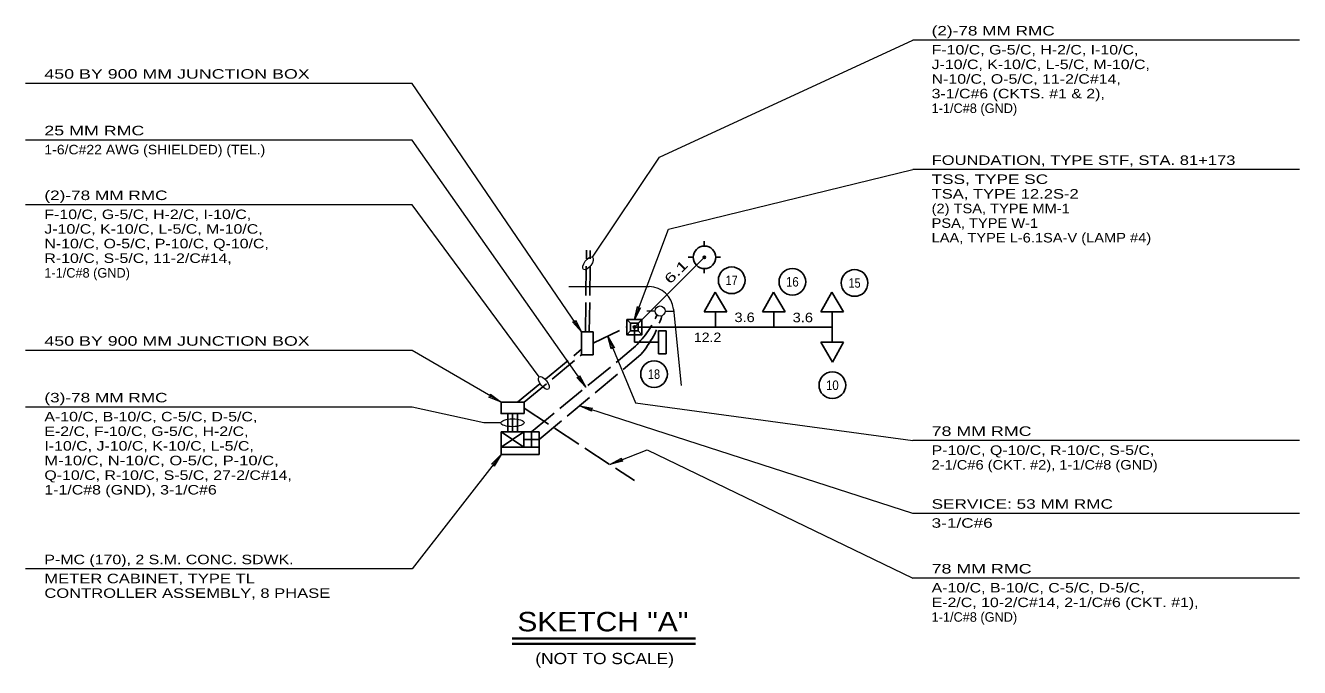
# Model space of a CAD drawing. Extents: x 168203 to 169863, y 223196 to 223870.
# Drawn here: x 168650.9 to 168729.5, y 223388.5 to 223428.2 of the extents above; entities that cross this region are included whole.
import ezdxf
from ezdxf.enums import TextEntityAlignment as Align

# ---------------------------------------------------------------- set-up
doc = ezdxf.new("R2010")
doc.units = 0
doc.header["$LTSCALE"] = 0.3
doc.header["$PDMODE"] = 32
doc.header["$PDSIZE"] = 0.15
doc.linetypes.add('LONG_DASH_SHORT_DASH', pattern=[9.9, 6, -1.2, 1.5, -1.2])
doc.linetypes.add('LONG_DASHED', pattern=[7.5, 6, -1.5])
for name, color, linetype, lineweight in [('1', 7, 'Continuous', 13), ('3', 7, 'Continuous', 25), ('31', 7, 'Continuous', 25), ('5', 7, 'Continuous', 25), ('6', 7, 'LONG_DASHED', 25), ('7', 7, 'Continuous', 25), ('9', 7, 'Continuous', 13)]:
    doc.layers.add(name, color=color, linetype=linetype, lineweight=lineweight)

msp = doc.modelspace()

# ---------------------------------------------------------------- linework, layer by layer
at = {"layer": '1'}
for p, q in [((168684.4082, 223412.0372), (168689.3593, 223412.0372)), ((168689.7236, 223410.5295), (168689.2236, 223410.5295)), ((168690.3486, 223410.5295), (168690.8486, 223410.5295)), ((168690.8555, 223410.6453), (168691.3411, 223405.9231))]:
    msp.add_line(p, q, dxfattribs=at)
msp.add_circle((168690.0361, 223410.5295), 0.3125, dxfattribs=at)
msp.add_arc((168689.3593, 223410.5372), 1.5, 4.13349, 90.00005, dxfattribs=at)
at = {"layer": '3'}
for p, q in [((168687.9774, 223410.0071), (168688.2123, 223409.7721)), ((168688.9171, 223410.0071), (168688.6822, 223409.7721)), ((168687.9774, 223409.0673), (168688.2123, 223409.3023)), ((168688.9171, 223409.0673), (168688.6822, 223409.3023))]:
    msp.add_line(p, q, dxfattribs=at)
for points in [[(168687.9774, 223410.0071), (168688.9171, 223410.0071), (168688.9171, 223409.0673), (168687.9774, 223409.0673)], [(168688.2123, 223409.7721), (168688.6822, 223409.7721), (168688.6822, 223409.3023), (168688.2123, 223409.3023)]]:
    msp.add_lwpolyline(points, close=True, dxfattribs=at)
msp.add_point((168688.4563, 223409.5372), dxfattribs=at)
at = {"layer": '31'}
for p, q in [((168688.4563, 223409.5372), (168692.7697, 223413.8506)), ((168693.4563, 223409.5372), (168693.4563, 223410.477)), ((168697.0563, 223409.5372), (168697.0563, 223410.477)), ((168700.6563, 223409.5372), (168700.6563, 223410.477)), ((168688.4563, 223409.5372), (168700.6563, 223409.5372)), ((168688.4563, 223408.5974), (168688.4563, 223409.5372)), ((168700.6563, 223409.5372), (168700.6563, 223408.5974)), ((168688.4563, 223408.5974), (168689.9392, 223408.5974))]:
    msp.add_line(p, q, dxfattribs=at)
at = {"layer": '31', "linetype": 'LONG_DASH_SHORT_DASH'}
for points in [[(168693.4382, 223411.6968), (168692.7515, 223410.477), (168693.4563, 223410.477), (168694.1611, 223410.477)], [(168697.0382, 223411.6968), (168696.3515, 223410.477), (168697.0563, 223410.477), (168697.7611, 223410.477)], [(168700.6382, 223411.6968), (168699.9515, 223410.477), (168700.6563, 223410.477), (168701.3611, 223410.477)], [(168690.409, 223407.8835), (168690.409, 223409.3022), (168689.9392, 223409.3022), (168689.9392, 223407.8835)], [(168700.6744, 223407.3776), (168701.3611, 223408.5974), (168700.6563, 223408.5974), (168699.9515, 223408.5974)]]:
    msp.add_lwpolyline(points, close=True, dxfattribs=at)
at = {"layer": '31'}
for centre in [(168694.4555, 223412.4268), (168698.2014, 223412.3337), (168702.0404, 223412.2639), (168689.6626, 223406.6306), (168700.669, 223405.9457)]:
    msp.add_circle(centre, 0.8236, dxfattribs=at)
at = {"layer": '5'}
for p, q in [((168680.2184, 223403.0683), (168681.628, 223402.1285)), ((168681.628, 223403.0683), (168680.2184, 223402.1285)), ((168680.2184, 223403.0683), (168682.5678, 223403.0683)), ((168680.2184, 223403.0683), (168680.2184, 223402.1285)), ((168681.628, 223402.1285), (168681.628, 223403.0683)), ((168681.628, 223402.5984), (168682.5678, 223402.5984)), ((168682.1069, 223403.0683), (168682.1069, 223402.1285)), ((168682.5678, 223403.0683), (168682.5678, 223402.1285)), ((168682.5678, 223402.1285), (168680.2184, 223402.1285)), ((168680.2184, 223402.1285), (168680.2184, 223401.6586)), ((168682.5678, 223402.1285), (168682.5678, 223401.6586)), ((168682.5678, 223401.6586), (168680.2184, 223401.6586))]:
    msp.add_line(p, q, dxfattribs=at)
for points in [[(168685.9002, 223409.2466), (168685.9002, 223407.8279), (168685.1954, 223407.8279), (168685.1954, 223409.2466)], [(168681.6376, 223404.1893), (168680.2189, 223404.1893), (168680.2189, 223404.8941), (168681.6376, 223404.8941)]]:
    msp.add_lwpolyline(points, close=True, dxfattribs=at)
at = {"layer": '6'}
for p, q in [((168685.4307, 223409.2466), (168685.4911, 223414.2809)), ((168685.669, 223409.2466), (168685.7294, 223414.2781)), ((168685.9002, 223408.5373), (168687.9774, 223409.5372)), ((168681.2373, 223404.8941), (168685.1954, 223408.1662)), ((168682.1069, 223403.0683), (168688.4013, 223408.2467)), ((168681.6376, 223404.8941), (168685.1864, 223407.8279)), ((168682.5678, 223402.5984), (168688.8574, 223407.8459)), ((168680.6326, 223404.1893), (168680.6326, 223403.0683)), ((168680.9282, 223404.1893), (168680.9282, 223403.0683)), ((168681.232, 223404.1893), (168681.232, 223403.0683)), ((168681.6376, 223404.5372), (168688.4522, 223400.0552))]:
    msp.add_line(p, q, dxfattribs=at)
for centre, radius, start, end in [((168684.0978, 223412.8293), 6.2865, 313.20139, 336.09784), ((168683.7004, 223412.1673), 6.7282, 320.03766, 343.32646)]:
    msp.add_arc(centre, radius, start, end, dxfattribs=at)
at = {"layer": '7'}
for p, q in [((168692.7569, 223414.5406), (168692.7633, 223414.8538)), ((168691.7601, 223413.8506), (168692.0796, 223413.8506)), ((168693.4726, 223413.8506), (168693.7601, 223413.8569)), ((168692.7634, 223412.8602), (168692.757, 223413.1477))]:
    msp.add_line(p, q, dxfattribs=at)
msp.add_circle((168692.7729, 223413.8474), 0.6965, dxfattribs=at)
msp.add_point((168692.7697, 223413.8506), dxfattribs=at)
at = {"layer": '9'}
for p, q in [((168729.5032, 223427.2662), (168705.6297, 223427.2662)), ((168674.7418, 223424.5965), (168650.8683, 223424.5965)), ((168685.1864, 223409.2466), (168674.7418, 223424.5965)), ((168674.7418, 223421.0965), (168650.8683, 223421.0965)), ((168685.4457, 223405.8152), (168674.7418, 223421.0965)), ((168729.5032, 223419.2662), (168705.6297, 223419.2662)), ((168674.7418, 223417.0965), (168650.8683, 223417.0965)), ((168682.5718, 223406.4583), (168674.7418, 223417.0965)), ((168674.7418, 223408.0965), (168650.8683, 223408.0965)), ((168680.2189, 223404.8941), (168674.7418, 223408.0965)), ((168674.7418, 223404.5965), (168650.8683, 223404.5965)), ((168705.6297, 223398.0247), (168685.0632, 223404.6804)), ((168729.5032, 223402.5247), (168705.6297, 223402.5247)), ((168680.2184, 223401.6586), (168674.7418, 223394.5965)), ((168729.5032, 223398.0247), (168705.6297, 223398.0247)), ((168674.7418, 223394.5965), (168650.8683, 223394.5965)), ((168729.5032, 223394.0247), (168705.6297, 223394.0247))]:
    msp.add_line(p, q, dxfattribs=at)
at = {"layer": '9', "lineweight": 35}
for p, q in [((168680.917, 223390.3044), (168692.2328, 223390.3044)), ((168680.917, 223389.957), (168692.2328, 223389.957))]:
    msp.add_line(p, q, dxfattribs=at)
at = {"layer": '9'}
for points in [[(168685.8686, 223413.8609), (168689.9984, 223420.0364), (168705.6297, 223427.2662)], [(168688.4473, 223410.0071), (168690.5609, 223415.5865), (168705.6297, 223419.2662)], [(168686.8076, 223408.9741), (168688.5107, 223404.8546), (168705.6297, 223402.5247)], [(168680.2142, 223403.6181), (168679.151, 223403.618), (168674.7418, 223404.5965)], [(168686.9396, 223401.05), (168689.248, 223401.9513), (168705.6297, 223394.0247)]]:
    msp.add_lwpolyline(points, dxfattribs=at)
for points in [[(168688.8284, 223410.7324), (168688.4473, 223410.0071), (168688.634, 223410.8061), (168688.7066, 223410.6915)], [(168684.8111, 223409.9749), (168685.1864, 223409.2466), (168684.6393, 223409.858), (168684.7747, 223409.8517)], [(168687.0265, 223408.1845), (168686.8076, 223408.9741), (168687.2185, 223408.2639), (168687.0872, 223408.2977)], [(168685.0605, 223406.5384), (168685.4457, 223405.8152), (168684.8903, 223406.4191), (168685.0258, 223406.4147)], [(168679.567, 223405.3904), (168680.2189, 223404.8941), (168679.4621, 223405.211), (168679.5871, 223405.2635)], [(168685.8064, 223404.3354), (168685.0632, 223404.6804), (168685.8704, 223404.5331), (168685.7595, 223404.4551)], [(168679.6414, 223401.0768), (168680.2184, 223401.6586), (168679.8057, 223400.9495), (168679.7699, 223401.0802)], [(168687.7334, 223401.2532), (168686.9396, 223401.05), (168687.6578, 223401.4468), (168687.6214, 223401.3162)]]:
    msp.add_lwpolyline(points, close=True, dxfattribs=at)
for centre, major_axis, ratio in [((168685.593, 223413.4775), (-0.2756, -0.3835), 0.453047), ((168682.864, 223406.0826), (-0.2922, 0.3757), 0.448277), ((168680.9282, 223403.6243), (0.714, 0.0062), 0.338213)]:
    msp.add_ellipse(centre, major_axis=major_axis, ratio=ratio, dxfattribs=at)

# ---------------------------------------------------------------- texts
at = {"layer": '31', "width": 1.5}
msp.add_text('6.1', height=0.5873, rotation=45, dxfattribs=at).set_placement((168691.231, 223412.7362), align=Align.CENTER)
at = {"layer": '31'}
for s, width, p in [('17', 0.85, (168694.4555, 223412.1332)), ('16', 0.9, (168698.2014, 223412.0401)), ('15', 0.85, (168702.0404, 223411.9703)), ('3.6', 1.15, (168695.2532, 223409.8468)), ('3.6', 1.15, (168698.8479, 223409.8372)), ('12.2', 1.1, (168692.969, 223408.6108)), ('18', 0.85, (168689.6626, 223406.337)), ('10', 0.9, (168700.669, 223405.6521))]:
    msp.add_text(s, height=0.5873, dxfattribs=dict(at, width=width)).set_placement(p, align=Align.CENTER)
at = {"layer": '9'}
for s, height, width, p in [('(2)-78 MM RMC                        ', 0.5873, 1.35, (168706.7954, 223427.5554)), ('F-10/C, G-5/C, H-2/C, I-10/C,', 0.5873, 1.25, (168706.7954, 223426.3807)), ('450 BY 900 MM JUNCTION BOX           ', 0.5873, 1.4, (168652.034, 223424.8857)), ('J-10/C, K-10/C, L-5/C, M-10/C,', 0.5873, 1.25, (168706.7954, 223425.477)), ('N-10/C, O-5/C, 11-2/C#14,  ', 0.5873, 1.25, (168706.7954, 223424.5734)), ('3-1/C#6 (CKTS. #1 & 2),  ', 0.5873, 1.25, (168706.7954, 223423.6698)), ('25 MM RMC                            ', 0.5873, 1.4, (168652.034, 223421.3857)), ('1-6/C#22 AWG (SHIELDED) (TEL.)        ', 0.5873, 1.1, (168652.034, 223420.211)), ('FOUNDATION, TYPE STF, STA. 81+173     ', 0.5873, 1.3, (168706.7954, 223419.5554)), ('TSS, TYPE SC                         ', 0.5873, 1.35, (168706.7954, 223418.3807)), ('(2)-78 MM RMC                        ', 0.5873, 1.35, (168652.034, 223417.3857)), ('TSA, TYPE 12.2S-2                    ', 0.5873, 1.3, (168706.7954, 223417.477)), ('F-10/C, G-5/C, H-2/C, I-10/C,', 0.5873, 1.25, (168652.034, 223416.211)), ('(2) TSA, TYPE MM-1                   ', 0.5873, 1.15, (168706.7954, 223416.5734)), ('J-10/C, K-10/C, L-5/C, M-10/C,', 0.5873, 1.25, (168652.034, 223415.3073)), ('PSA, TYPE W-1                    ', 0.5873, 1.15, (168706.7954, 223415.6698)), ('LAA, TYPE L-6.1SA-V (LAMP #4)         ', 0.5873, 1.15, (168706.7954, 223414.7662)), ('N-10/C, O-5/C, P-10/C, Q-10/C,  ', 0.5873, 1.25, (168652.034, 223414.4037)), ('R-10/C, S-5/C, 11-2/C#14,       ', 0.5873, 1.25, (168652.034, 223413.5001)), ('450 BY 900 MM JUNCTION BOX           ', 0.5873, 1.4, (168652.034, 223408.3857)), ('(3)-78 MM RMC                          ', 0.5873, 1.35, (168652.034, 223404.8857)), ('A-10/C, B-10/C, C-5/C, D-5/C,', 0.5873, 1.25, (168652.034, 223403.711)), ('E-2/C, F-10/C, G-5/C, H-2/C,  ', 0.5873, 1.25, (168652.034, 223402.8073)), ('78 MM RMC                            ', 0.5873, 1.4, (168706.7954, 223402.8139)), ('I-10/C, J-10/C, K-10/C, L-5/C,', 0.5873, 1.25, (168652.034, 223401.9037)), ('P-10/C, Q-10/C, R-10/C, S-5/C,', 0.5873, 1.25, (168706.7954, 223401.6392)), ('M-10/C, N-10/C, O-5/C, P-10/C, ', 0.5873, 1.3, (168652.034, 223401.0001)), ('2-1/C#6 (CKT. #2), 1-1/C#8 (GND)   ', 0.5873, 1.15, (168706.7954, 223400.7355)), ('Q-10/C, R-10/C, S-5/C, 27-2/C#14, ', 0.5873, 1.25, (168652.034, 223400.0965)), ('1-1/C#8 (GND), 3-1/C#6           ', 0.5873, 1.25, (168652.034, 223399.1929)), ('SERVICE: 53 MM RMC                   ', 0.5873, 1.35, (168706.7954, 223398.3139)), ('3-1/C#6                               ', 0.5873, 1.35, (168706.7954, 223397.1392)), ('P-MC (170), 2 S.M. CONC. SDWK.         ', 0.5873, 1.25, (168652.034, 223394.8857)), ('78 MM RMC                            ', 0.5873, 1.4, (168706.7954, 223394.3139)), ('METER CABINET, TYPE TL               ', 0.5873, 1.3, (168652.034, 223393.711)), ('CONTROLLER ASSEMBLY, 8 PHASE         ', 0.5873, 1.3, (168652.034, 223392.8073)), ('A-10/C, B-10/C, C-5/C, D-5/C,', 0.5873, 1.25, (168706.7954, 223393.1392)), ('E-2/C, 10-2/C#14, 2-1/C#6 (CKT. #1), ', 0.5873, 1.25, (168706.7954, 223392.2355)), ('(NOT TO SCALE)', 0.6958, 1.15, (168682.3351, 223388.7115))]:
    msp.add_text(s, height=height, dxfattribs=dict(at, width=width)).set_placement(p)
for s, p in [('1-1/C#8 (GND)           ', (168706.7954, 223422.7662)), ('1-1/C#8 (GND)                  ', (168652.034, 223412.5965)), ('1-1/C#8 (GND)                       ', (168706.7954, 223391.3318))]:
    msp.add_text(s, height=0.5873, dxfattribs=at).set_placement(p)
at = {"layer": '9', "width": 1.15}
msp.add_text('SKETCH "A"', height=1.202, dxfattribs=at).set_placement((168686.5083, 223390.7381), align=Align.CENTER)

doc.saveas('drawing.dxf')
